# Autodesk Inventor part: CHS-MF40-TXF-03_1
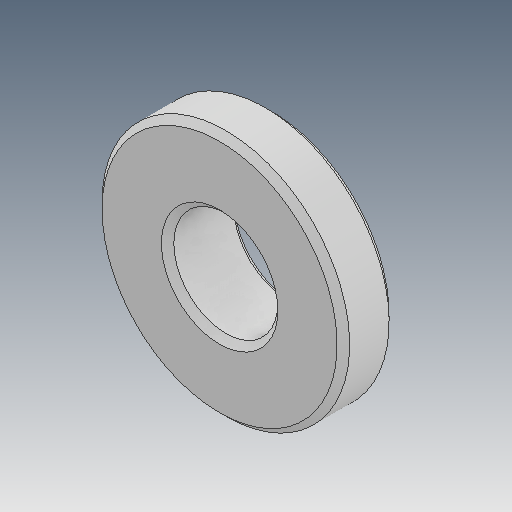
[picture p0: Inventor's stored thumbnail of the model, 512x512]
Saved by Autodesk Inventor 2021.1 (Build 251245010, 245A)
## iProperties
Created: 2019-05
Part Number: CHS-MF40-TXF-03_1
Material: Ogólny
Document SubType Name: Modeling
Designer: user
Density: 1 g/cm^3
Appearance: Domyślna
Author: user
Revision Number: ÈÎºÎ
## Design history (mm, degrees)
feature "ÊäÈë1"
node "Bryła1"
